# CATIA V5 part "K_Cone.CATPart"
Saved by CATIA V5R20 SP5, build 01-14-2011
Part number: Cone
Bounding box of the stored display mesh (mm): x -20 to 20, y -40 to 26.581, z -20 to 20
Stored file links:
  G:\Khaled_CFAO_2011\ST2M\ST2M_GR2\amorin\Khaled\CAD_Modification\K_Cone.CATPart
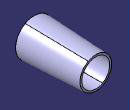
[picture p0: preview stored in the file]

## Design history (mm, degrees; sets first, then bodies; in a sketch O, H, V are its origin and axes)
Body1 (main body)
  Sketch1 on yz-plane, origin (0, 0, 0), H (0, 1, 0), V (0, 0, 1)
    line L1 (-40, 15) -> (26.5809, 15)
    line L2 (-40, 15) -> (-40, 20)
    point P3 (-40, 20)
    line L3 (26.5809, 15) -> (26.5809, 17)
    point P4 (26.5809, 17)
    line L4 (-40, 20) -> (26.5809, 17)
    distance L1 H = 15
    distance P3 H = 20
    distance P4 H = 17
    horizontal: L1 H
    vertical: L2 V, L3 V
  Shaft1: profile Sketch1, axis Sketch1.H, angle 360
